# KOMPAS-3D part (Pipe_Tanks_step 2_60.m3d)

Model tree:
1. X Axis
2. Y Axis
3. Z Axis  (labels: Valve Dy 50; Pipe Dn 50)
     Òîëùèíà ñòåíêè 1 = 1

Referenced files in C:\Documents and Settings\kashirsky\Мои документы\Camtasia Studio\Pipelines3D\Tanks\: Tanks_step 2.a3d
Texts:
  Pipe Dn 50
  Steel ASTM A295
  Three Point Plane
  Plane at Angle
  Line and Point Plane
  Axis through Two Vertices
  Axis of Feature
  Axis of Conical Surface
  Axis through Edge
  Trim by Surface
  Trim by Sketch
  Feature with No History
  Intersection Axis of Two Planes
  Two Line Plane
  Line and Face Plane
  Bend by line
  Hole in sheet body
  Cut in sheet body
  Point in CM
  Linear Dimension from Line to Point
  Surface Finish Symbol
  Geometric Tolerance Symbol
  Leader #1
  Leader #2
  Leader #3
  Shape Deviations and Datum
  Node point number
  Mark of coordination axis
  Node point designation
  Mark/Reference designation with leader
  Mark/reference designation on line
  Mark/Reference designation without leader
  Valve Dy 50
  Plane of section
